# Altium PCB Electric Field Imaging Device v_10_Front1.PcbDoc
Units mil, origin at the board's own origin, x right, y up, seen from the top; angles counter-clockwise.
Board outline 3543.31 x 2165.35 mil, 2 copper layers (Top Layer, Bottom Layer); 1 components, 0 nets, 16 pads, 0 vias.
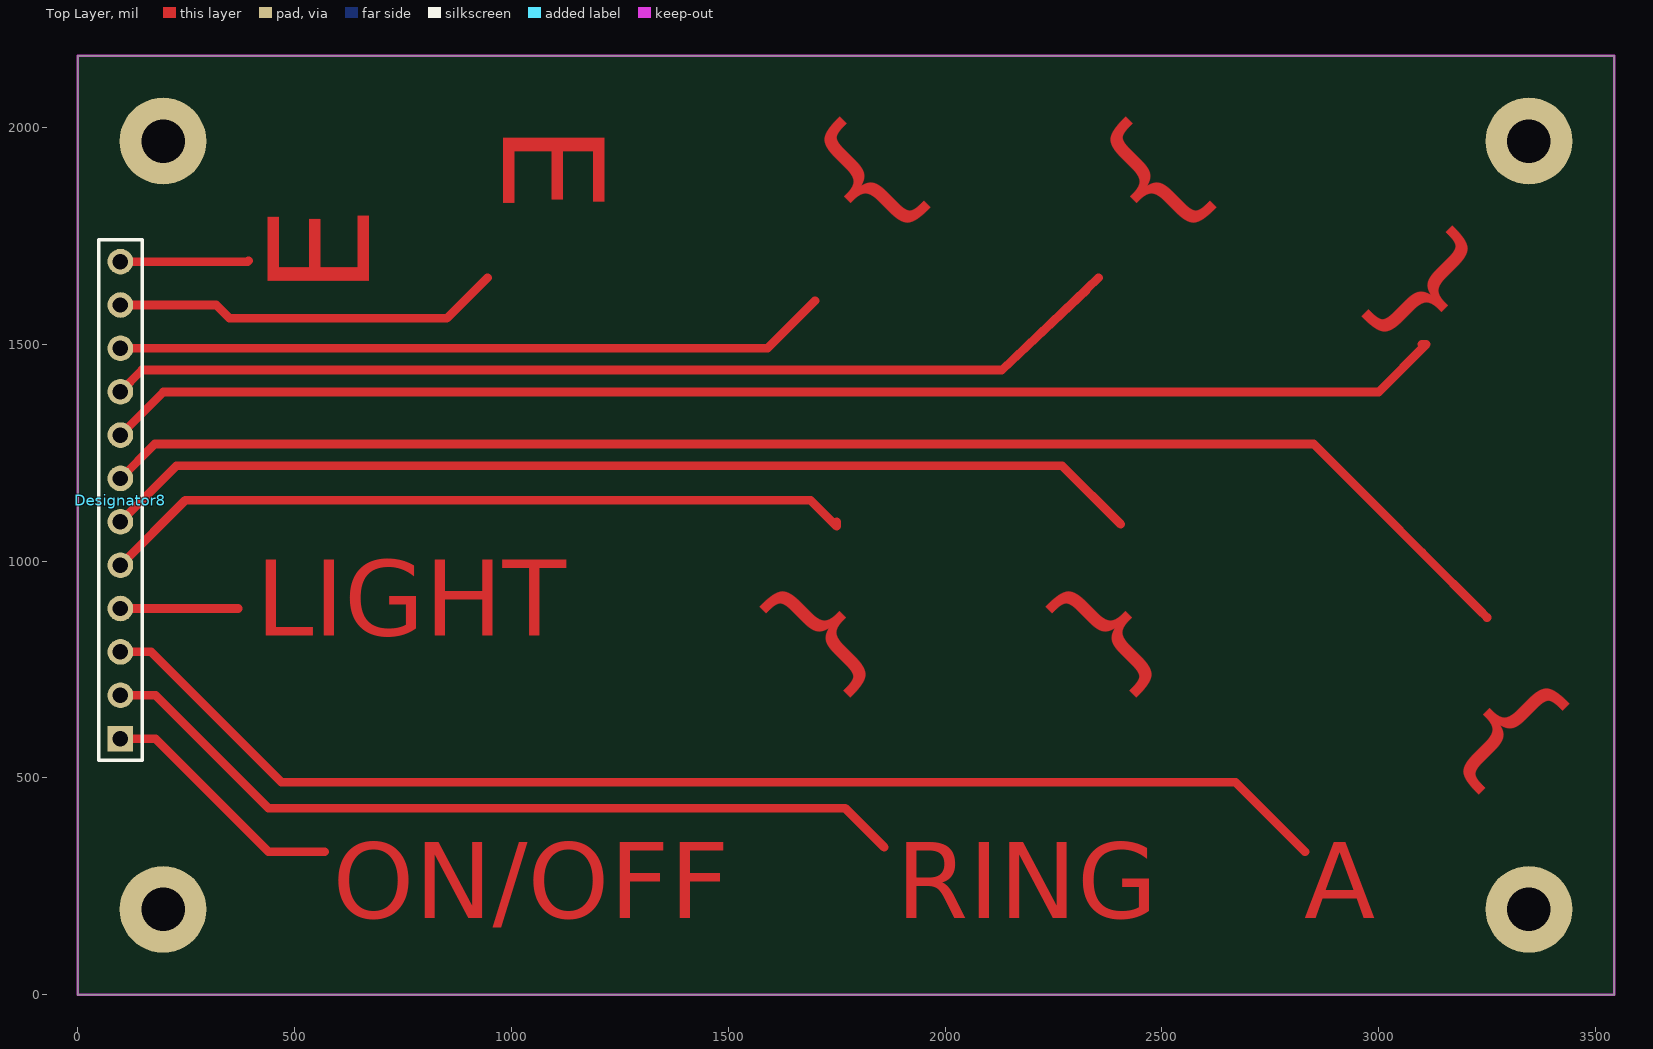
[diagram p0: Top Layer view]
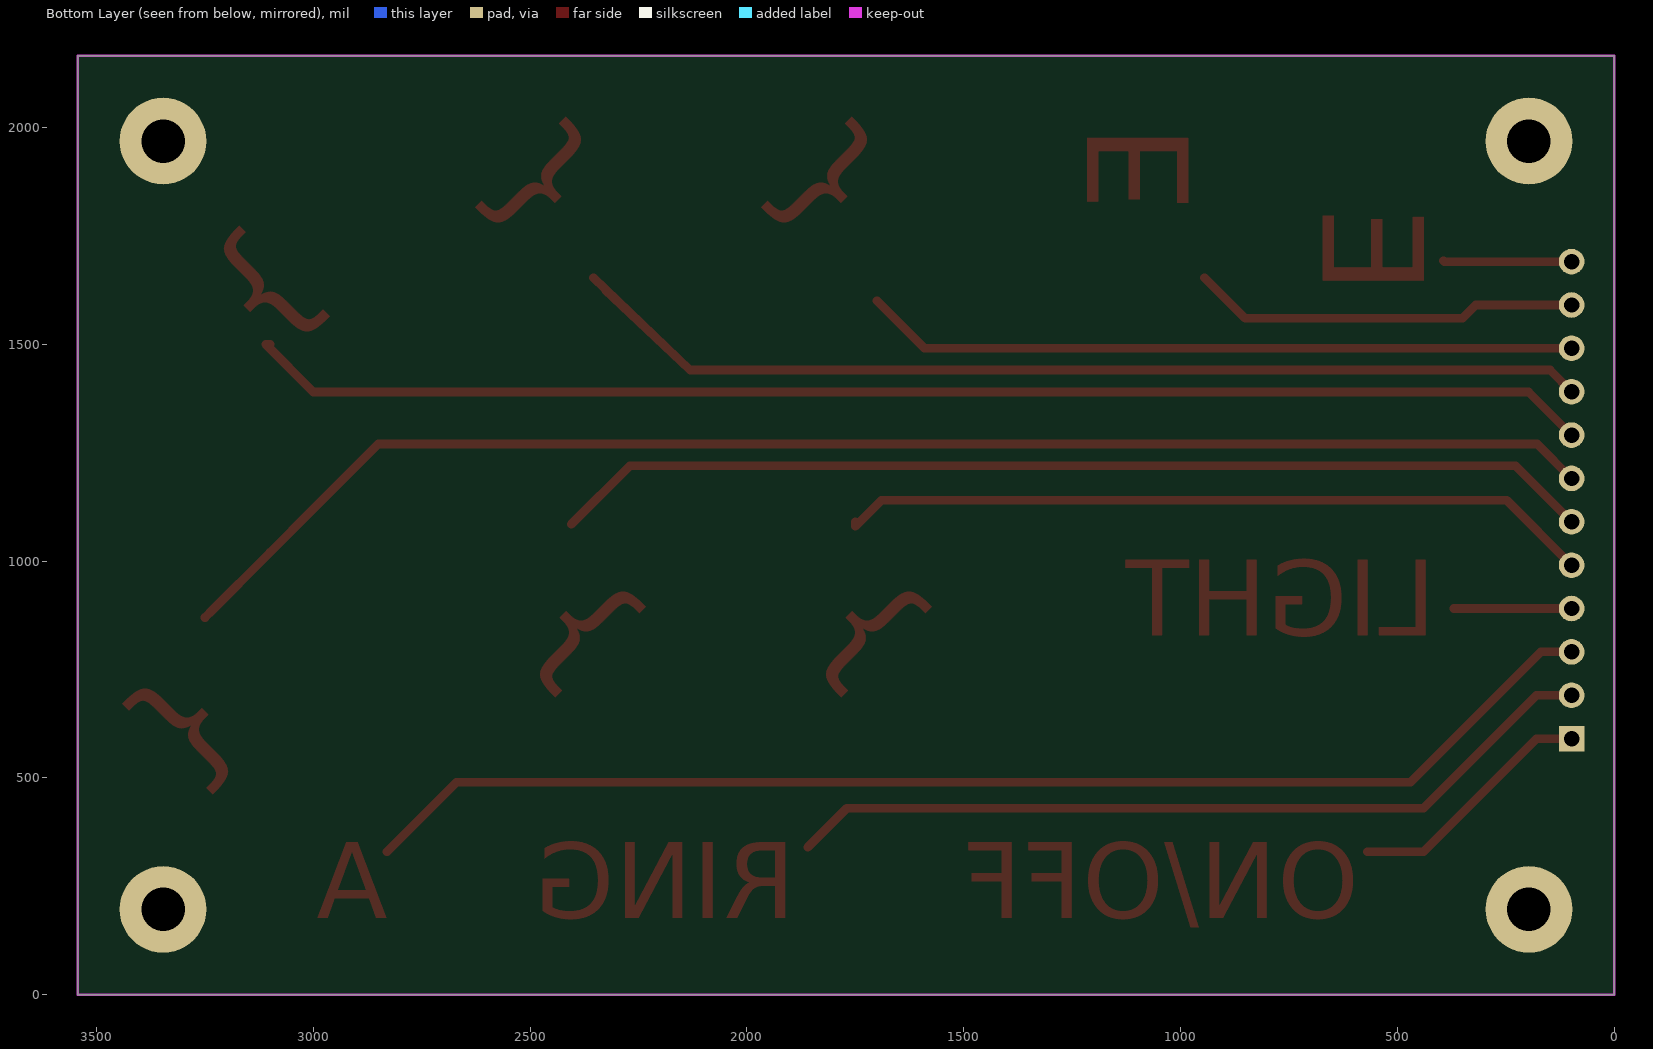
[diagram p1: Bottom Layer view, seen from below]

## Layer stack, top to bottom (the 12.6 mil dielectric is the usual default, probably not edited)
Top Layer: signal copper 1.4
Dielectric: dielectric 12.6, FR-4, Dk 4.8
Bottom Layer: signal copper 1.4

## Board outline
0,0 3543.31,0 3543.31,2165.35 0,2165.35 0,0

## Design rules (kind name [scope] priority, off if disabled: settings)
Clearance [All] p1 off: gap=10
ComponentClearance [All] p1 off: gap=10 collisioncheckmode=3 verticalgap=10 showdistances=FALSE
HoleSize [All] p1 off: absolutevalues=TRUE maxlimit=100 minlimit=1 maxpercent=80.000 minpercent=20.000
LayerPairs [All] p1 off: enforce=TRUE
PolygonConnect [All] p1: connectstyle=Relief reliefconductorwidth=10 reliefentries=4 polygonreliefangle="90 Angle"
RoutingCorners [All] p1 off: cornerstyle=45-Degree minsetback=100 maxsetback=100
RoutingLayers [All] p1 off: top layer_v5=TRUE bottom layer_v5=TRUE
RoutingPriority [All] p1 off: routingpriority=0
RoutingTopology [All] p1 off: topology=Shortest
RoutingVias [All] p1 off: holewidth=28 width=50 viastyle="Through Hole" minholewidth=28 minwidth=50 maxholewidth=28 maxwidth=50
ShortCircuit [All] p1 off: allowed=FALSE
SolderMaskExpansion [All] p1 off: expansion=4
TestPointUsage [All] p1 off: valid=0 allowmultiple=FALSE
Testpoint [All] p1 off: side=15 testpointundercomponent=TRUE minsize=40 maxsize=100 preferedsize=60 minholesize=0 maxholesize=40 preferedholesize=32 testpointgrid=1 style=1023 order=0123456789
UnRoutedNet [All] p1 off:
Width [All] p1: maxlimit=100 minlimit=10 preferedwidth=10 minimp=50.000000 maximp=50.000000 favimp=50.000000
10 further rules are at their usual default settings.

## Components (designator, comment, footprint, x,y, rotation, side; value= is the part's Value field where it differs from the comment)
Designator8 "Comment" HDR1X12 98.43,590.55 r90 top

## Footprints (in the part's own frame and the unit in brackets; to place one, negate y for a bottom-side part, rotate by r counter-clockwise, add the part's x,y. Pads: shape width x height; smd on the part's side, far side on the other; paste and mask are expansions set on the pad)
HDR1X12 [mm] "Connector; Header; 12 Position"
  rect 1.5x1.5 hole 0.9: 1(0,0)
  round 1.5 hole 0.9: 2(2.54,0) 3(5.08,0) 4(7.62,0) 5(10.16,0) 6(12.7,0) 7(15.24,0) 8(17.78,0) 9(20.32,0) 10(22.86,0) 11(25.4,0) 12(27.94,0)
  silkscreen extent -1.27,-1.27 29.21,1.27

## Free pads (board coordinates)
  round 200 hole 100: 0(196.85,196.85) 0(196.85,1968.5) 0(3346.46,196.85) 0(3346.46,1968.5)

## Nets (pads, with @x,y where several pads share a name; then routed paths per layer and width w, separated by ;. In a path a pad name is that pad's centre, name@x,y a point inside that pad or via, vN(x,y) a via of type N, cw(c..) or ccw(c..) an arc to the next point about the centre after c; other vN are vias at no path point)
pads on no net: Designator8.1 Designator8.2 Designator8.3 Designator8.4 Designator8.5 Designator8.6 Designator8.7 Designator8.8 Designator8.9 Designator8.10 Designator8.11 Designator8.12
copper on no net: | length 22313.7
  Top Layer w20: 98.43,590.55 179.45,590.55 440,330 570,330 ; 98.43,690.55 179.45,690.55 440,430 1770,430 1860,340 ; 98.43,790.55 169.45,790.55 470,490 2670,490 2830,330 ; 98.43,890.55 370,890.55 ; 98.43,990.55 247.87,1140 1450,1140 1580,1140 ; 98.43,1090.55 227.87,1220 2160,1220 2270,1220 2405,1085 ; 98.43,1190.55 177.87,1270 2340,1270 2850,1270 3250,870 ; 98.43,1290.55 197.87,1390 2480,1390 3000,1390 3110,1500 3100,1500 ; 98.43,1390.55 148.43,1440.55 2010,1440.55 ; 98.43,1490.55 1480.55,1490.55 1590.55,1490.55 ; 98.43,1690.55 391.34,1690.55 393.7,1692.91 ; 259.84,1590.55 98.43,1590.55 319.45,1590.55 350,1560 851.34,1560 944.88,1653.54 ; 1595.95,1495.95 1590.55,1490.55 ; 1650,1140 1560,1140 1690,1140 1750,1080 1750,1090 ; 1700,1600 1590.55,1490.55 ; 2021.1,1440.55 2010,1440.55 ; 2326.73,1626.18 2131.1,1440.55 ; 2354.09,1653.54 2131.1,1440.55 ; 2590,1390 2640,1390 ; 3100,1020 3240,880 ; 2010,1440.55 2131.1,1440.55

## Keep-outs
Keep-Out Layer:
  the board outline again, w5

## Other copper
Top Layer:
  text "}" at 1770,2070 h400 r225
  text "}" at 2430,2070 h400 r225
  text "E" at 905.51,2007.87 h400 r270
  text "E" at 748.03,1614.17 h400 r90
  text "}" at 2916,1576 h400 r315
  text "LIGHT" at 410,770 h300
  text "}" at 3486,657.89 h400 r135
  text "}" at 1770,640 h400 r45
  text "}" at 2430,640 h400 r45
  text "ON/OFF" at 587.85,118.52 h300
  text "RING" at 1887.85,118.52 h300
  text "A" at 2827.85,118.52 h300

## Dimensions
98.43,1690.55 to 98.43,590.55 on Mechanical 1
0,0 to 98.43,590.55 on Mechanical 1
3543.31,0 to 3346.46,196.85 on Mechanical 1
3346.46,196.85 to 3543.31,0 on Mechanical 1
3543.31,2165.35 to 3346.46,1968.5 on Mechanical 1
3346.46,1968.5 to 3543.31,2165.35 on Mechanical 1
0,2165.35 to 196.85,1968.5 on Mechanical 1
196.85,1968.5 to 0,2165.35 on Mechanical 1
196.85,196.85 to 0,0 on Mechanical 1
0,0 to 196.85,196.85 on Mechanical 1
0,0 to 3543.31,0 on Mechanical 1
0,0 to 0,2165.35 on Mechanical 1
